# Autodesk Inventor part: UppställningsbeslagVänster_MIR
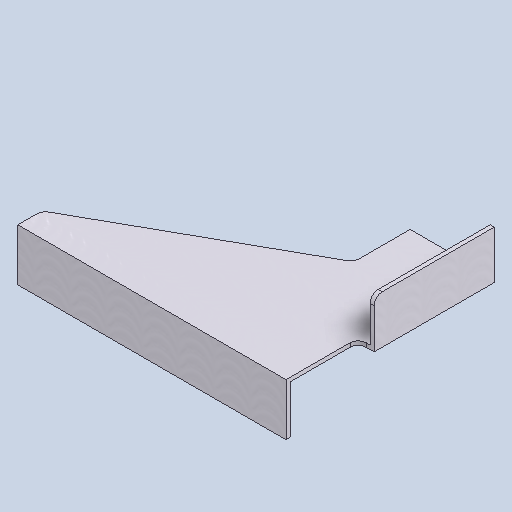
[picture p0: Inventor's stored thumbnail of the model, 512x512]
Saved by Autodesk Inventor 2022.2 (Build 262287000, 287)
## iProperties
Created: 2019-06
Part Number: UppställningsbeslagVänster_MIR
Material: Aluminum 6061, Welded
Document SubType Name: Modeling
Designer: cl
Density: 2.7 g/cm^3
Appearance: Weld - Aluminum
Author: cl
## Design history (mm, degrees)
derived "UppställningsbeslagVänster.ipt"
  sketch "Sketch1"
    geometry: L1 (0, 0)-(-100, 0) reference; L2 (-100, 0)-(-100, -70) reference; L3 (-100, -70)-(-350, -210) reference; L4 (-350, -210)-(-350, -240) reference; L5 (-350, -240)-(-15, -240) reference; L6 (-15, -240)-(-15, -150) reference; L7 (-15, -150)-(5, -150) reference; L8 (5, -150)-(5, 0) reference; L9 (5, 0)-(0, 0) reference
  sketch "Sketch2"
    geometry: L1 (-5, 150)-(5, 150) reference; L2 (-5, 150)-(0, 150) reference; L3 (0, 150)-(0, 0) reference; L4 (0, 0)-(-5, 0) reference; L5 (-5, 0)-(-5, 150) reference; 1 further point
  sketch "Sketch3"
    geometry: L1 (15, -240)-(350, -240) reference; L2 (350, -240)-(350, -215.861) reference; L3 (15, -240)-(350, -240) reference; L4 (350, -240)-(350, -235) reference; L5 (350, -235)-(15, -235) reference; L6 (15, -235)-(15, -240) reference; 2 further points
  sketch "Sketch4"
    geometry: L1 (0, 0)-(0, -60) reference; L2 (-335, -60)-(0, -60) reference; C1 r 20 at (-20, -30) reference; C2 r 15 at (-20, -30) reference; 1 further point
feature "Solid1::UppställningsbeslagVänster.ipt"
tag "TaggingFeature1"
body "Solid1"
